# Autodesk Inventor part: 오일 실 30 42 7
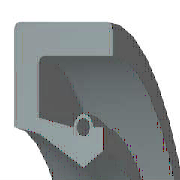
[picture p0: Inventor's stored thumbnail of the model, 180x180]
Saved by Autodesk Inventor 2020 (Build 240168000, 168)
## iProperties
Created: 2012-02
Part Number: 오일 실 30 42 7
Material: 고무
Description: 오일 실 - 스프링 장착, 금속 케이스 SM
Document SubType Name: Modeling
Standard: JIS B 2402
Designer: mdu-01
Standards Organization: JIS
Language: ko-KR
Size Designation: 30 42 7 A
Categories: <MemberInstance><Categories><Category DisplayName="샤프트 부품" InternalName="7f7aeb1f-a693-4053-b835-cee3144e0d98" Mnemonic="SHFT"><Category DisplayName="실링" Intern
Density: 0.93 g/cm^3
Appearance: Rubber-Black
Mass: 2.53106 g
Surface Area: 36.9849 cm^2
Volume: 2.72157 cm^3
IsCustomPart: 1
Author: mdu-01
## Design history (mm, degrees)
body "Solid1"
revolve "회전1" stored, may be unused: angle "d33" = 360 deg
fillet "모깎기1" dims "d34" = 0.35 (= 0.05 x b)
chamfer "모따기1" distance "d35" = 0.7 (= 0.1 x b); stored, may be unused: second distance "d36" = 0.35 (= 0.05 x b), angle "d41" = 45 deg
sketch "스케치2"
  geometry: L1 (16.457, -5.158)-(17.021, -7); L2 (15.857, -4.55)-(16.457, -5.158); L3 (15, -1.75)-(15.857, -4.55); L4 (15.8, -0.875)-(15, -1.75); L5 (17.141, -0.875)-(15.8, -0.875); L6 (17.141, -1.575)-(17.141, -0.875); L7 (17.141, -5.25)-(17.141, -2.975); L8 (18.6, -5.25)-(17.141, -5.25); L9 (19.8, -1.75)-(18.6, -5.25); L10 (19.8, 0)-(19.8, -1.75); L11 (21, 0)-(19.8, 0); L12 (21, -7)-(21, 0); L13 (17.021, -7)-(21, -7); L14 (0, -9.6)-(0, 1.6) reference; L15 (28, 0)-(14, 0) reference; A1 r 0.7 centre (17.141, -2.275) between (17.141, -2.975) and (17.141, -1.575)
  constraints: 26 end point, 4 horizontal, 4 vertical, 2 point on circle, 1 centre point, 1 collinear, 1 parallel
  dimensions: "d2" = 7 distance of L12.start L11.start (= b); "d4" = 0.875 vertical distance of L10.start L5.start (= 0.125 x b); "d6" = 1.2 distance of L11.start L10.start (= 0.1 x dd - 0.1 x Diam); "d8" = 1.75 distance of L10.start L9.start (= 0.25 x b); "d10" = 1.75 vertical distance of L8.start L1.end (= 0.25 x b); "d12" = 1.2 horizontal distance of L9.start L8.start (= 0.1 x dd - 0.1 x Diam); "d14" = 0.7 radius of A1 (= 0.1 x b); "d16" = 0 horizontal distance of A1.centre L7.end; "d18" = 0.7 distance of L6.start L5.start (= 0.1 x b); "d20" = 0.8 horizontal distance of L4.start L3.start (= 0.0666667 x dd - 0.0666667 x Diam); "d22" = 0.12 horizontal distance of L7.start L1.end (= 0.01 x dd - 0.01 x Diam); "d24" = 0.875 vertical distance of L4.start L3.start (= 0.125 x b); "d26" = 2.8 vertical distance of L3.start L2.start (= 0.4 x b); "d28" = 0.85714 horizontal distance of L3.start L2.start (= 0.0714286 x dd - 0.0714286 x Diam); "d30" = 1.84211 vertical distance of L1.start L1.end (= 0.263158 x b); "d32" = 0.6 horizontal distance of L2.start L1.start (= 0.05 x dd - 0.05 x Diam); "d37" = 0 distance between parallel lines of L15 L11; "d38" = 21 distance between parallel lines of L14 L12 (= 0.5 x dd); "d39" = 15 distance from line of L14 L3.start (= 0.5 x Diam)
other parameters: "dd" = 42 [user parameter; used in 7 equation terms], "b" = 7 [user parameter; used in 12 equation terms], "d1" = 8 (derived), "d3" = 1 (derived), "d5" = 2 (derived), "d7" = 2 (derived), "d9" = 2 (derived), "d11" = 2 (derived), "d13" = 0.8 (derived), "d15" = 0 (derived), "d17" = 0.8 (derived), "d19" = 1.33333 (derived), "d21" = 0.2 (derived), "d23" = 1 (derived), "d25" = 3.2 (derived), "d27" = 1.42857 (derived), "d29" = 2.10526 (derived), "d31" = 1 (derived), "d40" = 0
